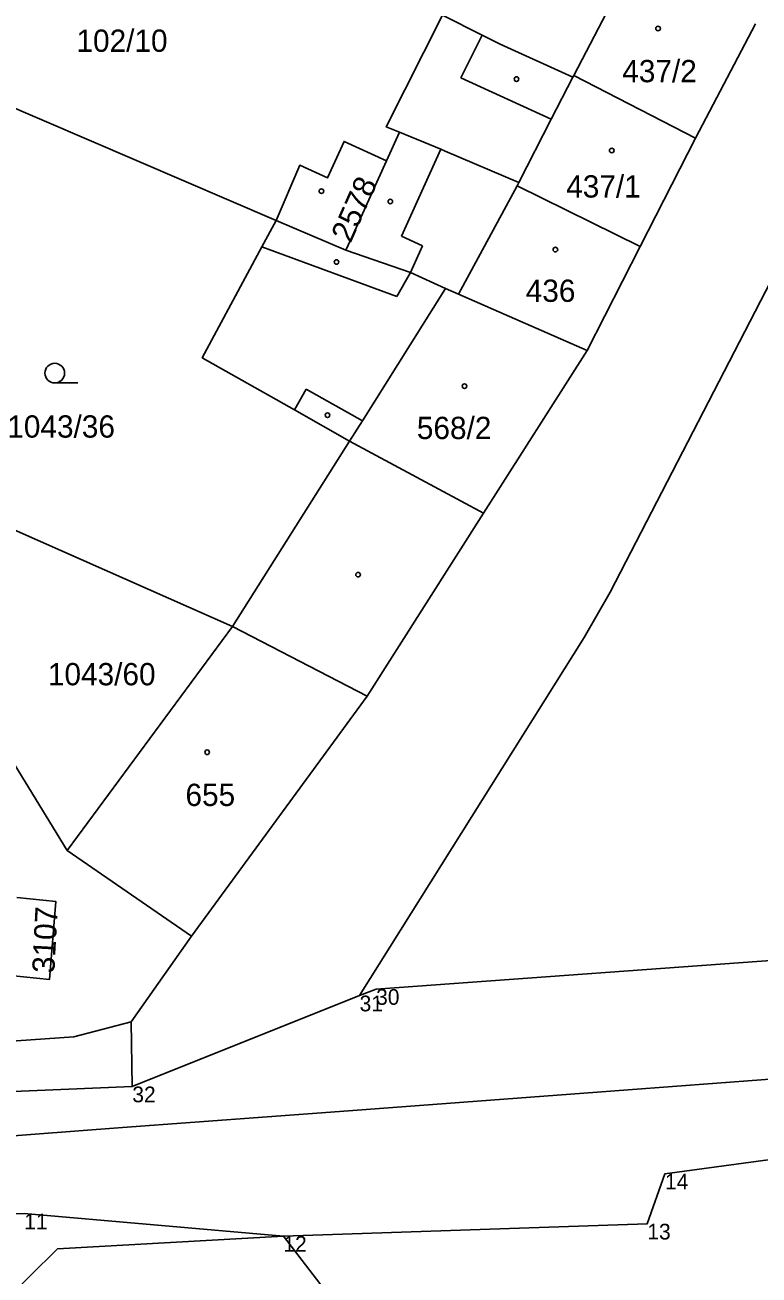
# Model space of a CAD drawing. Extents: x -779330 to -774454, y -1144748 to -1142831.
# Drawn here: x -775096.6 to -775040.6, y -1144462.2 to -1144366.8 of the extents above; entities that cross this region are included whole.
import ezdxf

# ---------------------------------------------------------------- set-up
doc = ezdxf.new("R2010")
doc.units = 0
for name, color, linetype in [('Hranice parcel', 7, 'Continuous'), ('Parcelní čísla', 7, 'Continuous'), ('SŽDC', 7, 'Continuous'), ('Vnitřní kresba', 7, 'Continuous'), ('Vrstva 1', 7, 'Continuous'), ('Vrstva 53', 7, 'Continuous'), ('Vrstva 60', 7, 'Continuous'), ('Značky budov', 7, 'Continuous'), ('Značky kultur', 7, 'Continuous')]:
    doc.layers.add(name, color=color, linetype=linetype)

msp = doc.modelspace()

# ---------------------------------------------------------------- linework, layer by layer
at = {"layer": 'Hranice parcel'}
for p, q in [((-775045.39, -1144375.46), (-775040.82, -1144366.72)), ((-775098.84, -1144372.52), (-775077.4, -1144381.72)), ((-775067.99, -1144374.98), (-775068.98, -1144377.17)), ((-775049.63, -1144383.72), (-775045.39, -1144375.46)), ((-775072.09, -1144383.99), (-775077.4, -1144381.72)), ((-775053.67, -1144391.64), (-775049.63, -1144383.72)), ((-775106.91, -1144401.13), (-775080.73, -1144412.7)), ((-775080.73, -1144412.7), (-775093.37, -1144429.8)), ((-775080.73, -1144412.7), (-775070.46, -1144418.03)), ((-775083.87, -1144436.35), (-775070.46, -1144418.03)), ((-775098.18, -1144421.94), (-775093.37, -1144429.8)), ((-775093.37, -1144429.8), (-775083.87, -1144436.35)), ((-775083.87, -1144436.35), (-775088.47, -1144442.87)), ((-775088.39, -1144447.82), (-775071.04, -1144440.88)), ((-775088.47, -1144442.87), (-775088.39, -1144447.82)), ((-775096.64, -1144457.51), (-775076.86, -1144459.23)), ((-775076.86, -1144459.23), (-775068.75, -1144469.74))]:
    msp.add_line(p, q, dxfattribs=at)
for points in [[(-774980.54, -1144260.84), (-774999.66, -1144289.45), (-775012.69, -1144325.05), (-775026.23, -1144360.34), (-775051.92, -1144410.08), (-775053.91, -1144413.55), (-775071.04, -1144440.88)], [(-775064.72, -1144366.06), (-775069, -1144374.59), (-775067.99, -1144374.98)], [(-775045.39, -1144375.46), (-775054.7, -1144370.66), (-775054.77, -1144370.8), (-775060.3, -1144368.27), (-775061.68, -1144367.58), (-775064.72, -1144366.06)], [(-775049.63, -1144383.72), (-775059.02, -1144379.08), (-775058.89, -1144378.83), (-775064.52, -1144376.43), (-775064.85, -1144376.29), (-775067.99, -1144374.98)], [(-775068.98, -1144377.17), (-775072.23, -1144375.69), (-775073.49, -1144378.48), (-775075.61, -1144377.52), (-775077.4, -1144381.72)], [(-775068.98, -1144377.17), (-775071.56, -1144382.85), (-775072.09, -1144383.99)], [(-775077.4, -1144381.72), (-775078.5, -1144383.75), (-775083.05, -1144392.2), (-775076.01, -1144396.19), (-775071.82, -1144398.57), (-775080.73, -1144412.7)], [(-775072.09, -1144383.99), (-775067.16, -1144385.69), (-775064.48, -1144386.93), (-775063.5, -1144387.36), (-775053.67, -1144391.64)], [(-775070.46, -1144418.03), (-775061.58, -1144404.07), (-775053.67, -1144391.64)], [(-775097.19, -1144433.38), (-775094.22, -1144433.7), (-775094.71, -1144439.66), (-775097.69, -1144439.34)], [(-774832.04, -1144435.58), (-774869.06, -1144438.3), (-774919.16, -1144442.27), (-774942.23, -1144444.12), (-775006.07, -1144448.84), (-775047.73, -1144454.47), (-775049.08, -1144458.29), (-775076.86, -1144459.23)], [(-775071.04, -1144440.88), (-775069.78, -1144440.38), (-775036.16, -1144437.94), (-775037.63, -1144440.85), (-775032.95, -1144440.83)], [(-775157.8, -1144448.55), (-775092.84, -1144444.02), (-775088.47, -1144442.87)], [(-775088.39, -1144447.82), (-775138.01, -1144449.91), (-775170.99, -1144453.66), (-775254.16, -1144459.9)]]:
    msp.add_lwpolyline(points, dxfattribs=at)
at = {"layer": 'SŽDC'}
for points in [[(-774890.46, -1144432.61), (-774957.77, -1144437.47), (-775003.31, -1144440.57), (-775006.9, -1144440.82), (-775032.95, -1144440.83), (-775037.63, -1144440.85), (-775036.16, -1144437.94), (-775069.78, -1144440.38), (-775071.04, -1144440.88), (-775088.39, -1144447.82), (-775138.01, -1144449.91), (-775170.99, -1144453.66), (-775254.16, -1144459.9), (-775301.48, -1144461.27), (-775337.71, -1144460.89), (-775341.64, -1144460.83), (-775351.35, -1144460.68), (-775377.95, -1144459.1), (-775417.93, -1144456.81), (-775426.17, -1144455.72)], [(-775425.39, -1144464.15), (-775389.68, -1144468.46), (-775332.79, -1144469.99), (-775289.7, -1144468.96), (-775237.91, -1144466.56), (-775217.76, -1144465.11), (-775204.62, -1144464.16), (-775201.24, -1144463.92), (-775137.35, -1144459.01), (-775096.64, -1144457.51), (-775076.86, -1144459.23), (-775049.08, -1144458.29), (-775047.73, -1144454.47), (-775006.07, -1144448.84), (-774942.23, -1144444.12), (-774919.16, -1144442.27)]]:
    msp.add_lwpolyline(points, dxfattribs=at)
at = {"layer": 'Vnitřní kresba'}
for p, q in [((-775050.12, -1144361.87), (-775054.7, -1144370.66)), ((-775061.68, -1144367.58), (-775063.31, -1144370.85)), ((-775063.31, -1144370.85), (-775056.42, -1144374)), ((-775054.77, -1144370.8), (-775056.42, -1144374)), ((-775056.42, -1144374), (-775058.89, -1144378.83)), ((-775067.85, -1144382.93), (-775064.85, -1144376.29)), ((-775059.02, -1144379.08), (-775063.5, -1144387.36)), ((-775066.24, -1144383.66), (-775067.85, -1144382.93)), ((-775078.5, -1144383.75), (-775068.21, -1144387.54)), ((-775067.16, -1144385.69), (-775066.24, -1144383.66)), ((-775068.21, -1144387.54), (-775067.16, -1144385.69)), ((-775064.48, -1144386.93), (-775070.83, -1144397.01)), ((-775075.11, -1144394.6), (-775076.01, -1144396.19)), ((-775070.83, -1144397.01), (-775075.11, -1144394.6)), ((-775070.83, -1144397.01), (-775071.82, -1144398.57)), ((-775071.82, -1144398.57), (-775061.58, -1144404.07)), ((-775094.1, -1144460.2), (-775076.86, -1144459.23)), ((-775094.1, -1144460.2), (-775111.21, -1144477.04))]:
    msp.add_line(p, q, dxfattribs=at)
at = {"layer": 'Vrstva 1'}
msp.add_lwpolyline([(-774830.163, -1144431.482), (-774850.563, -1144433.022), (-774864.475, -1144434.064), (-774869.912, -1144434.473), (-774871.827, -1144434.617), (-774885.853, -1144435.682), (-774900.88, -1144436.804), (-774924.49, -1144438.587), (-774948.039, -1144440.364), (-774972.389, -1144442.197), (-774996.531, -1144444.018), (-775020.057, -1144445.789), (-775040.384, -1144447.314), (-775053.937, -1144448.326), (-775072.564, -1144449.732), (-775089.145, -1144450.956), (-775106.822, -1144452.299), (-775129.866, -1144454.038), (-775154.332, -1144455.872), (-775163.87, -1144456.589), (-775186.746, -1144458.314), (-775211.372, -1144460.168), (-775237.518, -1144462.13)], dxfattribs=at)
at = {"layer": 'Vrstva 53'}
for points in [[(-775426.17, -1144455.72), (-775417.93, -1144456.81), (-775377.95, -1144459.1), (-775351.35, -1144460.68), (-775341.64, -1144460.83), (-775337.71, -1144460.89), (-775301.48, -1144461.27), (-775254.16, -1144459.9), (-775170.99, -1144453.66), (-775138.01, -1144449.91), (-775088.39, -1144447.82), (-775071.04, -1144440.88), (-775069.78, -1144440.38), (-775036.16, -1144437.94), (-775037.63, -1144440.85), (-775032.95, -1144440.83), (-775006.9, -1144440.82), (-775003.31, -1144440.57), (-774957.77, -1144437.47), (-774890.46, -1144432.61)], [(-775426.17, -1144455.72), (-775417.93, -1144456.81), (-775377.95, -1144459.1), (-775351.35, -1144460.68), (-775341.64, -1144460.83), (-775337.71, -1144460.89), (-775301.48, -1144461.27), (-775254.16, -1144459.9), (-775170.99, -1144453.66), (-775138.01, -1144449.91), (-775088.39, -1144447.82), (-775071.04, -1144440.88), (-775069.78, -1144440.38), (-775036.16, -1144437.94), (-775037.63, -1144440.85), (-775032.95, -1144440.83), (-775006.9, -1144440.82), (-775003.31, -1144440.57), (-774957.77, -1144437.47), (-774890.46, -1144432.61)], [(-774919.16, -1144442.27), (-774942.23, -1144444.12), (-775006.07, -1144448.84), (-775047.73, -1144454.47), (-775049.08, -1144458.29), (-775076.86, -1144459.23), (-775096.64, -1144457.51), (-775137.35, -1144459.01), (-775201.24, -1144463.92), (-775204.62, -1144464.16), (-775217.76, -1144465.11), (-775237.91, -1144466.56), (-775289.7, -1144468.96), (-775332.79, -1144469.99)], [(-774919.16, -1144442.27), (-774942.23, -1144444.12), (-775006.07, -1144448.84), (-775047.73, -1144454.47), (-775049.08, -1144458.29), (-775076.86, -1144459.23), (-775096.64, -1144457.51), (-775137.35, -1144459.01), (-775201.24, -1144463.92), (-775204.62, -1144464.16), (-775217.76, -1144465.11), (-775237.91, -1144466.56), (-775289.7, -1144468.96), (-775332.79, -1144469.99)]]:
    msp.add_lwpolyline(points, dxfattribs=at)
at = {"layer": 'Vrstva 60'}
for p, q in [((-775071.04, -1144440.88), (-775071.04, -1144440.88)), ((-775069.78, -1144440.38), (-775069.78, -1144440.38)), ((-775088.39, -1144447.82), (-775088.39, -1144447.82)), ((-775047.73, -1144454.47), (-775047.73, -1144454.47)), ((-775049.08, -1144458.29), (-775049.08, -1144458.29)), ((-775076.86, -1144459.23), (-775076.86, -1144459.23))]:
    msp.add_line(p, q, dxfattribs=at)
at = {"layer": 'Značky budov'}
for centre in [(-775048.257, -1144367.079), (-775059.067, -1144370.939), (-775051.797, -1144376.389), (-775073.957, -1144379.489), (-775068.697, -1144380.279), (-775056.097, -1144383.949), (-775072.807, -1144384.899), (-775063.037, -1144394.369), (-775073.487, -1144396.589), (-775071.157, -1144408.759), (-775082.677, -1144422.309)]:
    msp.add_circle(centre, 0.175, dxfattribs=at)
at = {"layer": 'Značky kultur'}
msp.add_line((-775094.303, -1144394.13), (-775092.553, -1144394.13), dxfattribs=at)
msp.add_circle((-775094.303, -1144393.38), 0.75, dxfattribs=at)

# ---------------------------------------------------------------- texts
at = {"layer": 'Parcelní čísla'}
for s, p in [('102/10', (-775092.65, -1144368.86)), ('437/2', (-775050.99, -1144371.18)), ('437/1', (-775055.27, -1144379.98)), ('436', (-775058.36, -1144387.94)), ('1043/36', (-775097.93, -1144398.3)), ('568/2', (-775066.67, -1144398.41)), ('1043/60', (-775094.83, -1144417.2)), ('655', (-775084.33, -1144426.41))]:
    msp.add_text(s, height=1.7, dxfattribs=at).set_placement(p)
for s, rotation, p in [('2578', 66, (-775071.723, -1144383.505)), ('3107', 87, (-775094.342, -1144439.198))]:
    msp.add_text(s, height=1.7, rotation=rotation, dxfattribs=at).set_placement(p)
at = {"layer": 'Vrstva 60'}
for s, p in [('31', (-775071.04, -1144442.08)), ('30', (-775069.78, -1144441.58)), ('32', (-775088.39, -1144449.02)), ('14', (-775047.73, -1144455.67)), ('11', (-775096.64, -1144458.71)), ('13', (-775049.08, -1144459.49)), ('12', (-775076.86, -1144460.43))]:
    msp.add_text(s, height=1.2, dxfattribs=at).set_placement(p)

doc.saveas('drawing.dxf')
